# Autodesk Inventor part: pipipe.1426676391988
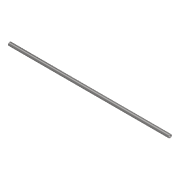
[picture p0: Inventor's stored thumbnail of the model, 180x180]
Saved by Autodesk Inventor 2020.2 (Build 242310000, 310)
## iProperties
Manager: www.cadconsulting.pl
Company: Fabian Stasiak CAD Consulting
NAME: PIPING: JIS G 3458 Pipe
DATA: <meta><inlinegroups number="1" deflen="10"></inlinegroups><connections number="2"></connections><angles><a>3.14159265358979</a></angles></meta>
IsCustomPart: 1
Created: 2015-03
Material: Stal, stopowa
Description: Rura
Document SubType Name: Modeling
Standard: JIS G 3458
Designer: F.Stasiak
Standards Organization: JIS
Language: pl-PL
Size Designation: 40 A x Sch 80 - 100
Categories: <MemberInstance><Categories><Category DisplayName="Rury cienko- i grubościenne" InternalName="4347fa0f-2144-441d-94cd-e3e15c92b736" Mnemonic="TUBEANDPIPE"><Cate
Stock Number: JIS G 3458 Rura 40 A x Sch 80
Density: 7.73 g/cm^3
Appearance: Częściowo polerowana
Catalog Web Link: www.expertbooks.pl
L: 2286,000 mm
PL: 2286,000 mm
Author: F.Stasiak
Subject: Zbiór ćwiczeń. Autodesk Inventor 2020. Kurs Professional
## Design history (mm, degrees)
sketch "Sketch1"
  geometry: C1 r 24.3 at (0, 0); C2 r 19.2 at (0, 0); 1 further point
  constraints: 2 centre point, 2 coincident, 1 concentric
  dimensions: "d0" = 48.6 diameter of C1 (= OD); "d1" = 38.4 diameter of C2 (= OD - 2 x t)
extrude "Extrusion1" new body sketch "Sketch1" distance "d2" = 2286 (= L); taper "d3" = 0 deg
workaxis "Work Axis1"
workpoint "Work Point1"
workaxis "Work Axis2"
workpoint "Work Point2"
body "Solid1"
other parameters: "OD" = 48.6 [user parameter; used in 2 equation terms], "t" = 5.1 [user parameter; used in 1 equation term], "L" = 2286 (= PL) [user parameter; used in 1 equation term], "ID" = 38.4 [user parameter], "PL" = 2286 [user parameter; used in 1 equation term], "Size_Designation" = 12.345 [user parameter]
